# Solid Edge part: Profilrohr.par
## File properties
Username: bmolnar
Dokumentum tartalom típus: 0
Author: bmolnar
Last saved by: bmolnar
Revision: 85
Sűrűség: 0,000 kg/m^3
Pontosság: 0,990
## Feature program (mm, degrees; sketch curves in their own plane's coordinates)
base feature "unnamed BaseFeature 1"
thread "unnamed Thread 1"
thread "Menet_2"  ThreadDepth = 5.3 mm
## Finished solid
Body 1: solid body, 157 faces, 364 edges, 230 vertices.
  Faces by surface: plane 72, cylinder 61, cone 20, torus 4
  Edges by curve: line 204, circle 148, spline 8, curve on surface 3, intersection 1
Bounding box of the edges (mm; curved faces can reach further): 36.000 x 40.000 x 88.000, from (-18, -18, 0) to (18, 22, 88).
Cylindrical faces by radius (mm): R0.3 x24, R0.8 x2, R2 x2, R2.067 x4, R2.9 x6, R4.4 x12, R10 x1, R10.8 x2, R10.9 x2, R11.4 x2, R23.75 x4
Conical faces (half-angle, radius in mm at the cone's reference point): 30 deg R10.8866 x1, 30 deg R10.9443 x1, 30 deg R10.9866 x2, 45 deg R2.417 x2, 45 deg R4.55 x12, 45 deg R10.25 x2
Toroidal faces (ring radius, tube radius in mm): R11.3 r0.1 x4
Planar faces by outward normal: +x 6, +y 9, +z 9, -x 6, -y 5, -z 9, oblique 28
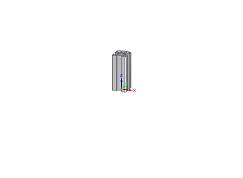
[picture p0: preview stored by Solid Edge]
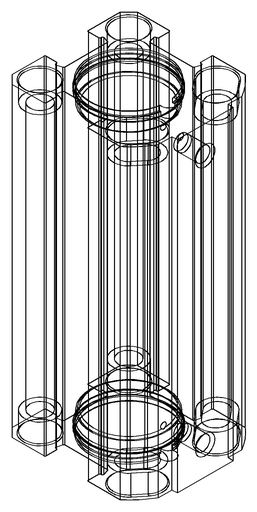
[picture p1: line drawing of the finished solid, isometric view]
